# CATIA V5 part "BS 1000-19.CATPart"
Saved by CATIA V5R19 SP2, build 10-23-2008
Part number: BS 1000-19
Bounding box of the stored display mesh (mm): x -24.865 to 24.865, y -24.997 to 24.997, z 0 to 76
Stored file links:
  C:\Users\Bora\Desktop\3D Katı model\BS serisi\BS 1000\BS 1000-19.CATPart
  C:\Program Files\Dassault Systemes\B19\intel_a\reffiles\standard\MetricThickPitch.txt
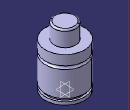
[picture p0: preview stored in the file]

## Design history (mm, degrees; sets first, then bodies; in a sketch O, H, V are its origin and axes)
Body1 (main body)
  Sketch1 on yz-plane, origin (0, 0, 0), H (0, 1, 0), V (0, 0, 1)
    point P2 (14, 74)
    line L1 (14, 74) -> (14, 56)
    point P3 (25, 43.5)
    line L2 (25, 56) -> (25, 43.5)
    point P6 (25, 39.5)
    line L3 (25, 39.5) -> (25, 7.5)
    line L4 (25, 4) -> (25, 0)
    point P9 (25, 39.5)
    point P10 (25, 43.5)
    arc A1 centre (25, 41.5) radius 2 from (25, 43.5) to (25, 39.5) ccw
    point P12 (14, 74)
    arc A2 centre (12, 74) radius 2 from (14, 74) to (12, 76) ccw
    point P13 (22.5, 4)
    point P14 (22.5, 4)
    line L5 (22.5, 7.5) -> (22.5, 4)
    line L6 (12, 76) -> (0, 76)
    point P16 (0, 76)
    line L7 (14, 56) -> (25, 56)
    line L8 (22.5, 7.5) -> (25, 7.5)
    line L9 (22.5, 4) -> (25, 4)
    line L10 (0, 0) -> (25, 0)
    coincidence: P16 V, P2 P12, P3 P10, P6 P9, P13 P14
    tangency: L6 A2
    horizontal: L7 H, L8 H, L9 H, L10 H
  Shaft1: profile Sketch1, axis Sketch1.V, angle 360
  Sketch2 on face of Shaft1 from Sketch1.L10, origin (0, 0, 0), H (1, 0, 0), V (0, -1, 0)
    point P1 (10, 0)
    distance P1 V = 10
  Hole1: placed by Sketch2, at (10, 0, 0) direction (0, 0, 1), diameter 6.647, depth 6, threaded "M8", thread diameter 8, thread depth 6, pitch 1.25
  CircPattern1: of Hole1, instances 2, angular step 180, axis from xy-plane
